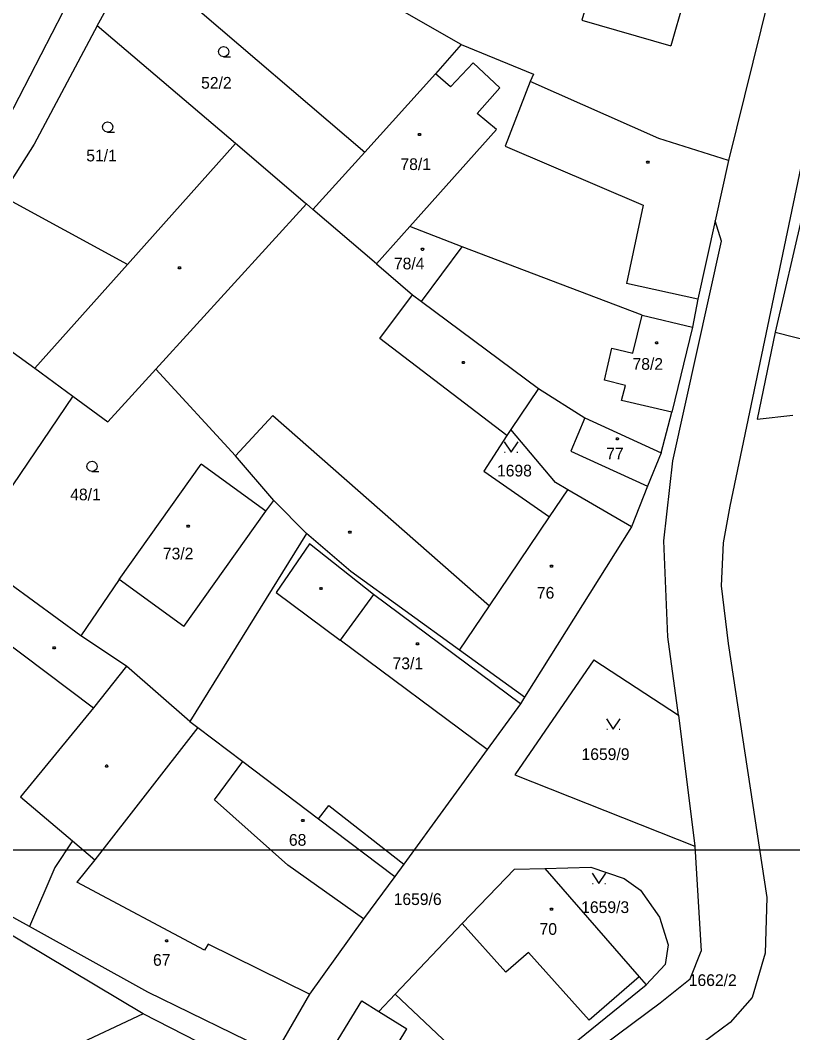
# Model space of a CAD drawing. Extents: x -802857 to -799647, y -1020285 to -1015884.
# Drawn here: x -801601.9 to -801490, y -1017640.2 to -1017493.5 of the extents above; entities that cross this region are included whole.
import ezdxf

# ---------------------------------------------------------------- set-up
doc = ezdxf.new("R2010")
doc.units = 0
for name, color, linetype in [('Default', 7, 'Continuous'), ('KN_HRANICE', 7, 'Continuous'), ('KN_KULTURY', 7, 'Continuous'), ('KN_PARCELY', 7, 'Continuous'), ('KN_SLUCKY', 7, 'Continuous'), ('LEGENDA', 7, 'Continuous')]:
    doc.layers.add(name, color=color, linetype=linetype)

# ---------------------------------------------------------------- blocks, each defined once
blk = doc.blocks.new('304')
at = {"layer": 'Default'}
blk.add_lwpolyline([(0, 0), (-0.38, 0.1), (-0.65, 0.37), (-0.75, 0.74), (-0.65, 1.11), (-0.38, 1.38), (-0.01, 1.48), (0.36, 1.38), (0.63, 1.11), (0.73, 0.73), (0.63, 0.35), (0.36, 0.08), (-0.02, -0.02), (0.98, -0.02)], dxfattribs=at)
blk = doc.blocks.new('314')
at = {"layer": 'Default'}
for p, q in [((-0.95, 0), (-0.85, 0)), ((0.85, 0), (0.95, 0))]:
    blk.add_line(p, q, dxfattribs=at)
blk.add_lwpolyline([(-1, 1.5), (0, 0), (1, 1.5)], dxfattribs=at)
blk = doc.blocks.new('NAHRADNI_SYMBOL')
at = {"layer": 'Default'}
blk.add_lwpolyline([(0.09, 0.15), (0.18, 0), (0.09, -0.15), (-0.09, -0.15), (-0.18, 0), (-0.09, 0.15), (0.09, 0.15)], dxfattribs=at)
blk = doc.blocks.new('402')
at = {"layer": 'Default'}
blk.add_lwpolyline([(0.09, 0.15), (0.18, 0), (0.09, -0.15), (-0.09, -0.15), (-0.18, 0), (-0.09, 0.15), (0.09, 0.15)], dxfattribs=at)

msp = doc.modelspace()

# ---------------------------------------------------------------- linework, layer by layer
at = {"layer": 'KN_HRANICE'}
for p, q in [((-801590.76, -1017494.27), (-801585.19, -1017484.18)), ((-801585.19, -1017484.18), (-801552, -1017512.59)), ((-801518.48, -1017486.31), (-801520.55, -1017493.48)), ((-801538.03, -1017497.01), (-801552.91, -1017488.45)), ((-801493.16, -1017489.06), (-801499.29, -1017513.8)), ((-801505.75, -1017490.62), (-801507.63, -1017497.2)), ((-801603.69, -1017507.7), (-801595.69, -1017492.25)), ((-801520.55, -1017493.48), (-801507.63, -1017497.2)), ((-801590.76, -1017494.27), (-801599.92, -1017511.43)), ((-801570.74, -1017511.34), (-801590.76, -1017494.27)), ((-801538.03, -1017497.01), (-801541.73, -1017501.25)), ((-801538.03, -1017497.01), (-801527.53, -1017501.29)), ((-801485.05, -1017496.6), (-801499.12, -1017563.93)), ((-801541.73, -1017501.25), (-801552, -1017512.59)), ((-801527.53, -1017501.29), (-801528.03, -1017502.37)), ((-801509.4, -1017510.64), (-801528.03, -1017502.37)), ((-801499.29, -1017513.8), (-801509.4, -1017510.64)), ((-801599.92, -1017511.43), (-801604.62, -1017518.91)), ((-801586.4, -1017528.88), (-801570.74, -1017511.34)), ((-801560.61, -1017519.98), (-801570.74, -1017511.34)), ((-801559.52, -1017520.91), (-801552, -1017512.59)), ((-801499.29, -1017513.8), (-801501.23, -1017522.53)), ((-801586.4, -1017528.88), (-801604.62, -1017518.91)), ((-801560.46, -1017520.1), (-801560.61, -1017519.98)), ((-801559.52, -1017520.91), (-801560.46, -1017520.1)), ((-801550.32, -1017528.8), (-801559.52, -1017520.91)), ((-801501.23, -1017522.53), (-801503.76, -1017533.9)), ((-801500.33, -1017525.52), (-801501.23, -1017522.53)), ((-801488.6, -1017521.78), (-801492.54, -1017538.69)), ((-801545.46, -1017523.36), (-801550.32, -1017528.8)), ((-801537.9, -1017526.32), (-801545.46, -1017523.36)), ((-801507.37, -1017557.32), (-801500.33, -1017525.52)), ((-801543.79, -1017534.25), (-801537.9, -1017526.32)), ((-801511.78, -1017536.22), (-801537.9, -1017526.32)), ((-801599.81, -1017543.92), (-801586.4, -1017528.88)), ((-801550.32, -1017528.8), (-801545.07, -1017533.3)), ((-801612.51, -1017534.74), (-801599.81, -1017543.92)), ((-801545.07, -1017533.3), (-801543.79, -1017534.25)), ((-801543.79, -1017534.25), (-801526.81, -1017546.86)), ((-801503.76, -1017533.9), (-801504.53, -1017537.97)), ((-801511.78, -1017536.22), (-801504.53, -1017537.97)), ((-801504.53, -1017537.97), (-801507.52, -1017550.31)), ((-801492.54, -1017538.69), (-801495.13, -1017551.32)), ((-801492.54, -1017538.69), (-801482.76, -1017541.15)), ((-801599.81, -1017543.92), (-801594.29, -1017547.96)), ((-801589.21, -1017551.68), (-801582.27, -1017544.05)), ((-801570.72, -1017556.63), (-801582.27, -1017544.05)), ((-801594.29, -1017547.96), (-801609.85, -1017570.88)), ((-801594.29, -1017547.96), (-801589.21, -1017551.68)), ((-801526.81, -1017546.86), (-801530.84, -1017552.81)), ((-801526.81, -1017546.86), (-801520.11, -1017551.13)), ((-801509.03, -1017556.19), (-801507.52, -1017550.31)), ((-801495.13, -1017551.32), (-801489.95, -1017550.72)), ((-801520.11, -1017551.13), (-801509.03, -1017556.19)), ((-801531.4, -1017553.68), (-801534.73, -1017558.85)), ((-801530.84, -1017552.81), (-801531.4, -1017553.68)), ((-801524.36, -1017560.49), (-801530.84, -1017552.81)), ((-801565.19, -1017563.07), (-801570.72, -1017556.63)), ((-801509.03, -1017556.19), (-801511.04, -1017561)), ((-801587.58, -1017574.55), (-801575.7, -1017557.81)), ((-801566.34, -1017564.62), (-801575.7, -1017557.81)), ((-801508.64, -1017568.95), (-801507.37, -1017557.32)), ((-801534.73, -1017558.85), (-801525.21, -1017565.48)), ((-801522.55, -1017561.54), (-801524.36, -1017560.49)), ((-801511.04, -1017561), (-801513.34, -1017566.91)), ((-801525.21, -1017565.48), (-801522.55, -1017561.54)), ((-801513.34, -1017566.91), (-801522.55, -1017561.54)), ((-801566.34, -1017564.62), (-801565.19, -1017563.07)), ((-801560.45, -1017567.88), (-801565.19, -1017563.07)), ((-801499.12, -1017563.93), (-801500.06, -1017569.23)), ((-801513.34, -1017566.91), (-801528.85, -1017591.59)), ((-801560.45, -1017567.88), (-801577.33, -1017595.14)), ((-801554.01, -1017573.4), (-801560.45, -1017567.88)), ((-801508.08, -1017582.87), (-801508.64, -1017568.95)), ((-801500.06, -1017569.23), (-801500.38, -1017575.48)), ((-801538.26, -1017584.79), (-801554.01, -1017573.4)), ((-801593.16, -1017582.7), (-801603.42, -1017575.18)), ((-801587.58, -1017574.55), (-801593.16, -1017582.7)), ((-801500.38, -1017575.48), (-801499.34, -1017583.8)), ((-801606.97, -1017581.38), (-801591.28, -1017593.15)), ((-801586.53, -1017587.13), (-801593.16, -1017582.7)), ((-801506.53, -1017594.21), (-801508.08, -1017582.87)), ((-801499.34, -1017583.8), (-801493.73, -1017620.66)), ((-801528.85, -1017591.59), (-801538.26, -1017584.79)), ((-801577.33, -1017595.14), (-801586.53, -1017587.13)), ((-801518.8, -1017586.17), (-801530.24, -1017602.86)), ((-801518.8, -1017586.17), (-801506.53, -1017594.21)), ((-801528.85, -1017591.59), (-801529.45, -1017592.57)), ((-801591.28, -1017593.15), (-801601.9, -1017606.03)), ((-801529.45, -1017592.57), (-801534.26, -1017599.18)), ((-801506.53, -1017594.21), (-801504.15, -1017613.18)), ((-801577.33, -1017595.14), (-801576.17, -1017596.02)), ((-801576.17, -1017596.02), (-801569.65, -1017600.94)), ((-801534.26, -1017599.18), (-801546.35, -1017615.83)), ((-801573.76, -1017606.48), (-801569.65, -1017600.94)), ((-801569.65, -1017600.94), (-801558.71, -1017609.22)), ((-801530.24, -1017602.86), (-801504.15, -1017613.18)), ((-801601.9, -1017606.03), (-801594.36, -1017612.44)), ((-801563.14, -1017615.95), (-801573.76, -1017606.48)), ((-801594.36, -1017612.44), (-801596.9, -1017616.29)), ((-801504.15, -1017613.18), (-801503.26, -1017628.41)), ((-801584.1, -1017637.52), (-801621.52, -1017615.14)), ((-801600.56, -1017624.82), (-801620.3, -1017614.03)), ((-801596.9, -1017616.29), (-801600.56, -1017624.82)), ((-801552.18, -1017623.73), (-801563.14, -1017615.95)), ((-801546.35, -1017615.83), (-801547.64, -1017617.6)), ((-801537.86, -1017624.4), (-801530.31, -1017616.54)), ((-801530.31, -1017616.54), (-801525.93, -1017616.44)), ((-801525.93, -1017616.44), (-801519.25, -1017616.26)), ((-801525.93, -1017616.44), (-801512.24, -1017632.12)), ((-801519.25, -1017616.26), (-801514.39, -1017617.87)), ((-801547.64, -1017617.6), (-801552.18, -1017623.73)), ((-801514.39, -1017617.87), (-801512.04, -1017619.58)), ((-801512.04, -1017619.58), (-801509.28, -1017623.48)), ((-801493.73, -1017620.66), (-801493.97, -1017628.73)), ((-801552.18, -1017623.73), (-801560.01, -1017634.67)), ((-801509.28, -1017623.48), (-801508.02, -1017627.49)), ((-801583.43, -1017634.37), (-801600.56, -1017624.82)), ((-801537.86, -1017624.4), (-801547.58, -1017634.67)), ((-801508.02, -1017627.49), (-801508.47, -1017630.35)), ((-801504.84, -1017632.45), (-801503.26, -1017628.41)), ((-801493.97, -1017628.73), (-801495.87, -1017635.14)), ((-801508.47, -1017630.35), (-801511.2, -1017633.31)), ((-801512.24, -1017632.12), (-801511.2, -1017633.31)), ((-801509.19, -1017635.93), (-801504.84, -1017632.45)), ((-801565.01, -1017643.36), (-801583.43, -1017634.37)), ((-801531.59, -1017649.73), (-801511.2, -1017633.31)), ((-801560.01, -1017634.67), (-801565.01, -1017643.36)), ((-801560.79, -1017649.3), (-801552.43, -1017635.64)), ((-801552.43, -1017635.64), (-801549.96, -1017637.17)), ((-801547.58, -1017634.67), (-801549.96, -1017637.17)), ((-801547.58, -1017634.67), (-801531.59, -1017649.73)), ((-801517.33, -1017641.94), (-801509.19, -1017635.93)), ((-801495.87, -1017635.14), (-801499.03, -1017638.78)), ((-801584.1, -1017637.52), (-801594.58, -1017642.43)), ((-801569.55, -1017644.94), (-801584.1, -1017637.52)), ((-801499.03, -1017638.78), (-801510.49, -1017647.16))]:
    msp.add_line(p, q, dxfattribs=at)
msp.add_lwpolyline([(-801558.71, -1017609.22), (-801557.22, -1017607.3), (-801546.35, -1017615.83)], dxfattribs=at)
at = {"layer": 'KN_SLUCKY'}
for p, q in [((-801536.3, -1017499.67), (-801539.59, -1017503.13)), ((-801532.44, -1017503.25), (-801536.3, -1017499.67)), ((-801539.59, -1017503.13), (-801541.73, -1017501.25)), ((-801528.03, -1017502.37), (-801531.64, -1017511.71)), ((-801535.69, -1017507), (-801532.44, -1017503.25)), ((-801532.9, -1017509.3), (-801535.69, -1017507)), ((-801545.46, -1017523.36), (-801532.9, -1017509.3)), ((-801531.64, -1017511.71), (-801511.64, -1017520.27)), ((-801582.27, -1017544.05), (-801560.46, -1017520.1)), ((-801511.64, -1017520.27), (-801514.07, -1017531.66)), ((-801503.76, -1017533.9), (-801514.07, -1017531.66)), ((-801549.8, -1017539.59), (-801545.07, -1017533.3)), ((-801513.15, -1017541.75), (-801511.78, -1017536.22)), ((-801531.4, -1017553.68), (-801549.8, -1017539.59)), ((-801517.27, -1017545.66), (-801516.18, -1017541.02)), ((-801516.18, -1017541.02), (-801513.15, -1017541.75)), ((-801514.23, -1017546.41), (-801517.27, -1017545.66)), ((-801514.78, -1017548.62), (-801514.23, -1017546.41)), ((-801507.52, -1017550.31), (-801514.78, -1017548.62)), ((-801565.3, -1017550.76), (-801570.72, -1017556.63)), ((-801565.3, -1017550.76), (-801533.92, -1017578.36)), ((-801520.11, -1017551.13), (-801522.12, -1017555.94)), ((-801522.12, -1017555.94), (-801511.04, -1017561)), ((-801578.22, -1017581.36), (-801566.34, -1017564.62)), ((-801533.92, -1017578.36), (-801525.21, -1017565.48)), ((-801560.01, -1017569.37), (-801564.85, -1017576.41)), ((-801550.75, -1017576.74), (-801560.01, -1017569.37)), ((-801578.22, -1017581.36), (-801587.58, -1017574.55)), ((-801564.85, -1017576.41), (-801555.56, -1017583.35)), ((-801550.75, -1017576.74), (-801555.56, -1017583.35)), ((-801529.45, -1017592.57), (-801550.75, -1017576.74)), ((-801538.26, -1017584.79), (-801533.92, -1017578.36)), ((-801534.26, -1017599.18), (-801555.56, -1017583.35)), ((-801586.53, -1017587.13), (-801591.28, -1017593.15)), ((-801576.17, -1017596.02), (-801591.13, -1017615.17)), ((-801558.71, -1017609.22), (-801547.64, -1017617.6)), ((-801594.36, -1017612.44), (-801591.13, -1017615.17)), ((-801591.13, -1017615.17), (-801593.7, -1017618.41)), ((-801575.23, -1017628.29), (-801593.7, -1017618.41)), ((-801531.55, -1017631.46), (-801537.86, -1017624.4)), ((-801574.67, -1017627.39), (-801575.23, -1017628.29)), ((-801560.01, -1017634.67), (-801574.67, -1017627.39)), ((-801528.27, -1017628.59), (-801531.55, -1017631.46)), ((-801519.47, -1017638.44), (-801528.27, -1017628.59)), ((-801512.24, -1017632.12), (-801519.47, -1017638.44)), ((-801549.96, -1017637.17), (-801545.89, -1017639.69)), ((-801550.3, -1017646.89), (-801545.89, -1017639.69))]:
    msp.add_line(p, q, dxfattribs=at)
at = {"layer": 'LEGENDA'}
msp.add_lwpolyline([(-801703.84, -1017613.71), (-800862.84, -1017613.71), (-800862.84, -1017019.71), (-801703.84, -1017019.71)], close=True, dxfattribs=at)

# ---------------------------------------------------------------- block references
at = {"layer": 'KN_KULTURY'}
for name, p in [('304', (-801572.44, -1017498.77)), ('304', (-801589.25, -1017509.68)), ('402', (-801544.06, -1017510.03)), ('402', (-801510.98, -1017514.05)), ('NAHRADNI_SYMBOL', (-801543.64, -1017526.68)), ('402', (-801578.84, -1017529.37)), ('402', (-801509.71, -1017540.23)), ('402', (-801537.72, -1017543.08)), ('314', (-801530.79, -1017556.09)), ('402', (-801515.39, -1017554.15)), ('304', (-801591.5, -1017558.88)), ('402', (-801577.59, -1017566.83)), ('402', (-801554.15, -1017567.69)), ('402', (-801524.95, -1017572.61)), ('402', (-801558.34, -1017575.85)), ('402', (-801597, -1017584.44)), ('402', (-801544.36, -1017583.86)), ('314', (-801515.99, -1017596.23)), ('402', (-801589.39, -1017601.58)), ('402', (-801560.98, -1017609.47)), ('314', (-801518.07, -1017618.63)), ('402', (-801524.95, -1017622.33)), ('402', (-801580.71, -1017626.93))]:
    msp.add_blockref(name, p, dxfattribs=at)

# ---------------------------------------------------------------- texts
at = {"layer": 'KN_PARCELY'}
for s, p in [('52/2', (-801575.71, -1017503.4)), ('51/1', (-801592.35, -1017513.94)), ('78/1', (-801546.83, -1017515.19)), ('78/4', (-801547.77, -1017529.59)), ('78/2', (-801513.2, -1017544.15)), ('77', (-801517.01, -1017557.12)), ('1698', (-801532.84, -1017559.61)), ('48/1', (-801594.68, -1017563.07)), ('73/2', (-801581.25, -1017571.63)), ('76', (-801527.06, -1017577.32)), ('73/1', (-801547.97, -1017587.55)), ('1659/9', (-801520.59, -1017600.71)), ('68', (-801562.99, -1017613.14)), ('1659/6', (-801547.81, -1017621.73)), ('1659/3', (-801520.64, -1017622.89)), ('70', (-801526.67, -1017626.05)), ('67', (-801582.68, -1017630.54)), ('1662/2', (-801505.05, -1017633.47))]:
    msp.add_text(s, height=1.7, dxfattribs=at).set_placement(p)

doc.saveas('drawing.dxf')
